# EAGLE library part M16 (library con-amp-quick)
AMP QUICK CONNECTOR
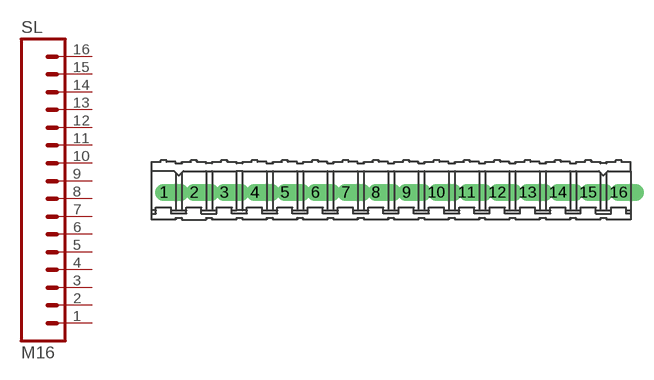
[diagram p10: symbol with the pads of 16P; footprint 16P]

Designator prefix SL

## M16  [16P]
1  1  pas
2  2  pas
3  3  pas
4  4  pas
5  5  pas
6  6  pas
7  7  pas
8  8  pas
9  9  pas
10  10  pas
11  11  pas
12  12  pas
13  13  pas
14  14  pas
15  15  pas
16  16  pas

## Footprint 16P (pad centres in mm)
AMP QUICK CONNECTOR
drill 0.914 offset: 1 -19.05,0; 2 -16.51,0; 3 -13.97,0; 4 -11.43,0; 5 -8.89,0; 6 -6.35,0; 7 -3.81,0; 8 -1.27,0; 9 1.27,0; 10 3.81,0; 11 6.35,0; 12 8.89,0; 13 11.43,0; 14 13.97,0; 15 16.51,0; 16 19.05,0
